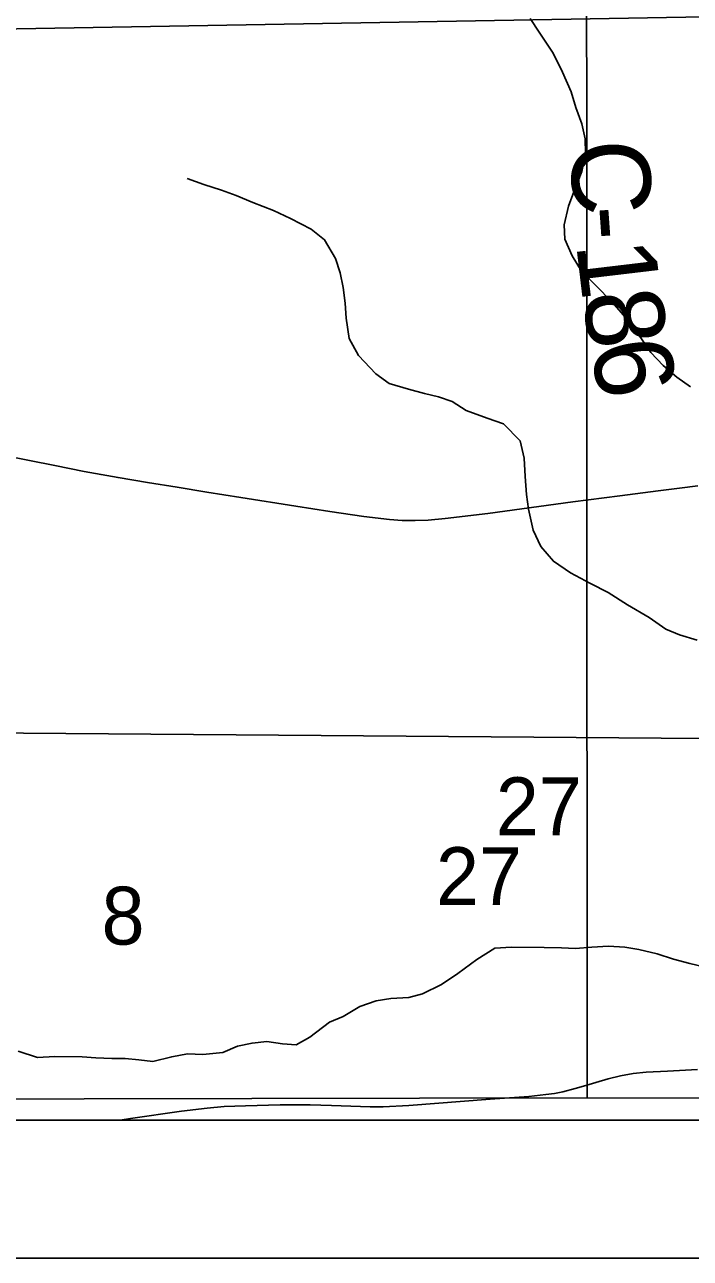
# Model space of a CAD drawing. Extents: x -21.1 to 50.3, y -4.9 to 22.1.
# Drawn here: x 6.007 to 6.488, y 14 to 14.892 of the extents above; entities that cross this region are included whole.
import ezdxf

# ---------------------------------------------------------------- set-up
doc = ezdxf.new("R2010")
doc.units = 0
for name, color, linetype in [('GM_X_Corporation', 7, 'Continuous'), ('GM_X_County', 7, 'Continuous'), ('GM_X_County_Road_Text', 7, 'Continuous'), ('GM_X_Minor_River', 7, 'Continuous'), ('GM_X_Rail_Line_Text', 7, 'Continuous'), ('GM_X_Section', 7, 'Continuous'), ('GM_X_Section_Text', 7, 'Continuous'), ('GM_X_Township_Road', 7, 'Continuous'), ('SH_Cut_Line', 7, 'Continuous'), ('SH_Data', 7, 'Continuous')]:
    doc.layers.add(name, color=color, linetype=linetype)

msp = doc.modelspace()

# ---------------------------------------------------------------- linework, layer by layer
at = {"layer": 'GM_X_Corporation'}
msp.add_lwpolyline([(5.92427, 14.1), (6.9316, 14.1), (6.92825, 14.37244), (5.91319, 14.38034)], close=True, dxfattribs=at)
at = {"layer": 'GM_X_County'}
msp.add_lwpolyline([(8.9, 14.74638), (8.9, 20.9), (2.1, 20.9), (2.1, 14.1), (8.89319, 14.1)], dxfattribs=at)
at = {"layer": 'GM_X_Minor_River'}
for points in [[(6.4881, 14.63012), (6.47827, 14.63701), (6.46846, 14.64541), (6.45942, 14.65495), (6.45265, 14.66486), (6.44288, 14.6782), (6.43308, 14.68926), (6.42291, 14.70033), (6.40934, 14.71369), (6.40258, 14.72473), (6.39735, 14.7369), (6.39666, 14.74715), (6.39978, 14.76079), (6.40364, 14.77101), (6.40943, 14.78577), (6.41218, 14.79903), (6.41186, 14.80928), (6.40966, 14.82029), (6.40519, 14.83208), (6.40185, 14.84348), (6.39549, 14.85756), (6.38875, 14.87126), (6.3786, 14.8865), (6.37222, 14.8964)], [(6.49295, 14.44684), (6.48008, 14.45072), (6.47024, 14.45495), (6.45815, 14.46337), (6.44265, 14.47257), (6.42867, 14.48139), (6.41581, 14.48791), (6.40144, 14.49559), (6.38898, 14.50401), (6.37994, 14.51469), (6.37433, 14.52649), (6.37101, 14.54168), (6.36956, 14.55232), (6.36851, 14.56522), (6.36784, 14.5785), (6.36489, 14.59104), (6.35282, 14.60326), (6.34109, 14.6075), (6.32594, 14.6129), (6.31574, 14.61942), (6.3059, 14.62289), (6.29567, 14.62523), (6.2843, 14.62834), (6.27029, 14.6326), (6.26047, 14.63949), (6.24804, 14.65284), (6.24128, 14.66503), (6.23911, 14.67983), (6.23842, 14.69046), (6.23697, 14.70185), (6.23477, 14.71249), (6.23142, 14.72275), (6.22354, 14.73646), (6.21372, 14.74411), (6.19897, 14.75179), (6.18649, 14.75755), (6.17173, 14.76334), (6.15962, 14.76834), (6.14902, 14.7722), (6.13615, 14.77645), (6.12403, 14.7807)], [(6.50088, 14.21006), (6.48761, 14.21318), (6.47587, 14.21629), (6.46413, 14.22015), (6.45087, 14.22327), (6.44064, 14.22485), (6.42888, 14.22568), (6.41673, 14.225), (6.40496, 14.22394), (6.39472, 14.22438), (6.3822, 14.22483), (6.35867, 14.22498), (6.34652, 14.22429), (6.33357, 14.21603), (6.31984, 14.20587), (6.30802, 14.19798), (6.29431, 14.19123), (6.28443, 14.18864), (6.27152, 14.18796), (6.26089, 14.18613), (6.24909, 14.18203), (6.2369, 14.17489), (6.22701, 14.17078), (6.2129, 14.15987), (6.20299, 14.15424), (6.19313, 14.15506), (6.18176, 14.15665), (6.17113, 14.15557), (6.16049, 14.15336), (6.14983, 14.14887), (6.1354, 14.14745), (6.1244, 14.14789), (6.113, 14.14569), (6.09932, 14.14236), (6.08908, 14.14356), (6.07922, 14.14438), (6.06973, 14.14444), (6.05797, 14.14489), (6.04811, 14.14571), (6.02838, 14.14583), (6.01585, 14.14515), (6.00184, 14.14979)]]:
    msp.add_lwpolyline(points, dxfattribs=at)
at = {"layer": 'GM_X_Rail_Line_Text'}
msp.add_lwpolyline([(2.87846, 14.1), (8.9, 14.1)], dxfattribs=at)
at = {"layer": 'GM_X_Section'}
for points in [[(6.50469, 15.92066), (6.49861, 14.89749), (5.48909, 14.88008), (5.47621, 15.91802), (5.53343, 15.91957)], [(5.4459, 15.12082), (6.41284, 15.11937), (6.41343, 14.11604), (5.44344, 14.11411)], [(6.41284, 15.11937), (7.42449, 15.11725), (7.43682, 14.11536), (6.41343, 14.11604)]]:
    msp.add_lwpolyline(points, close=True, dxfattribs=at)
at = {"layer": 'GM_X_Township_Road'}
for points in [[(5.99187, 14.58034), (6.02839, 14.57319), (6.04969, 14.56899), (6.0619, 14.56668), (6.07412, 14.56447), (6.09552, 14.56089), (6.11695, 14.55747), (6.13841, 14.55402), (6.16295, 14.55009), (6.20283, 14.54375), (6.22737, 14.53989), (6.25196, 14.53635), (6.27043, 14.53413), (6.27972, 14.53342), (6.28903, 14.53335), (6.29834, 14.53377), (6.31071, 14.53486), (6.34155, 14.5386), (6.40312, 14.54685), (6.43696, 14.55139), (6.4647, 14.55483), (6.48008, 14.55671), (6.49332, 14.5584)], [(6.07576, 14.1), (6.08313, 14.10121), (6.12006, 14.10631), (6.13854, 14.10865), (6.15091, 14.10967), (6.16643, 14.11037), (6.1913, 14.11094), (6.21307, 14.11102), (6.22861, 14.1106), (6.25658, 14.10941), (6.26589, 14.10945), (6.28441, 14.11056), (6.34324, 14.11499), (6.37115, 14.11708), (6.38351, 14.11837), (6.38966, 14.11923), (6.39574, 14.12042), (6.40473, 14.12272), (6.41069, 14.12445), (6.41959, 14.12719), (6.42851, 14.12982), (6.43754, 14.132), (6.44671, 14.13357), (6.45597, 14.13457), (6.47148, 14.13543), (6.49322, 14.13655)]]:
    msp.add_lwpolyline(points, dxfattribs=at)
at = {"layer": 'SH_Cut_Line'}
msp.add_lwpolyline([(2.1, 14.1), (8.9, 14.1)], dxfattribs=at)
at = {"layer": 'SH_Data'}
msp.add_line((2, 14), (9, 14), dxfattribs=at)

# ---------------------------------------------------------------- texts
at = {"layer": 'GM_X_County_Road_Text'}
for s, rotation, p in [('C', 272.77997, (6.40105, 14.80764)), ('-', 274.13081, (6.4034, 14.75957)), ('1', 276.7836, (6.40535, 14.73344)), ('8', 278.51939, (6.40974, 14.69682)), ('6', 280.69501, (6.41532, 14.65989))]:
    msp.add_text(s, height=0.05682, rotation=rotation, dxfattribs=at).set_placement(p)
at = {"layer": 'GM_X_Section_Text'}
for s, height, p in [('27', 0.041856, (6.34734, 14.30589)), ('27', 0.041856, (6.30405, 14.25537)), ('8', 0.04186, (6.0622, 14.22683))]:
    msp.add_text(s, height=height, rotation=0.00001, dxfattribs=at).set_placement(p)

doc.saveas('drawing.dxf')
